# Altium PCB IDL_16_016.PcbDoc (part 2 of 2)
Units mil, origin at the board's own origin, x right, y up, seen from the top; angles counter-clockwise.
Board outline 4921.26 x 4921.26 mil, 4 copper layers (Top Layer - SIG1, MID1_GND, MID2_PWR, Bottom Layer - SIG2), stack 60.174 mil thick; 186 components, 167 nets, 650 pads, 188 vias.
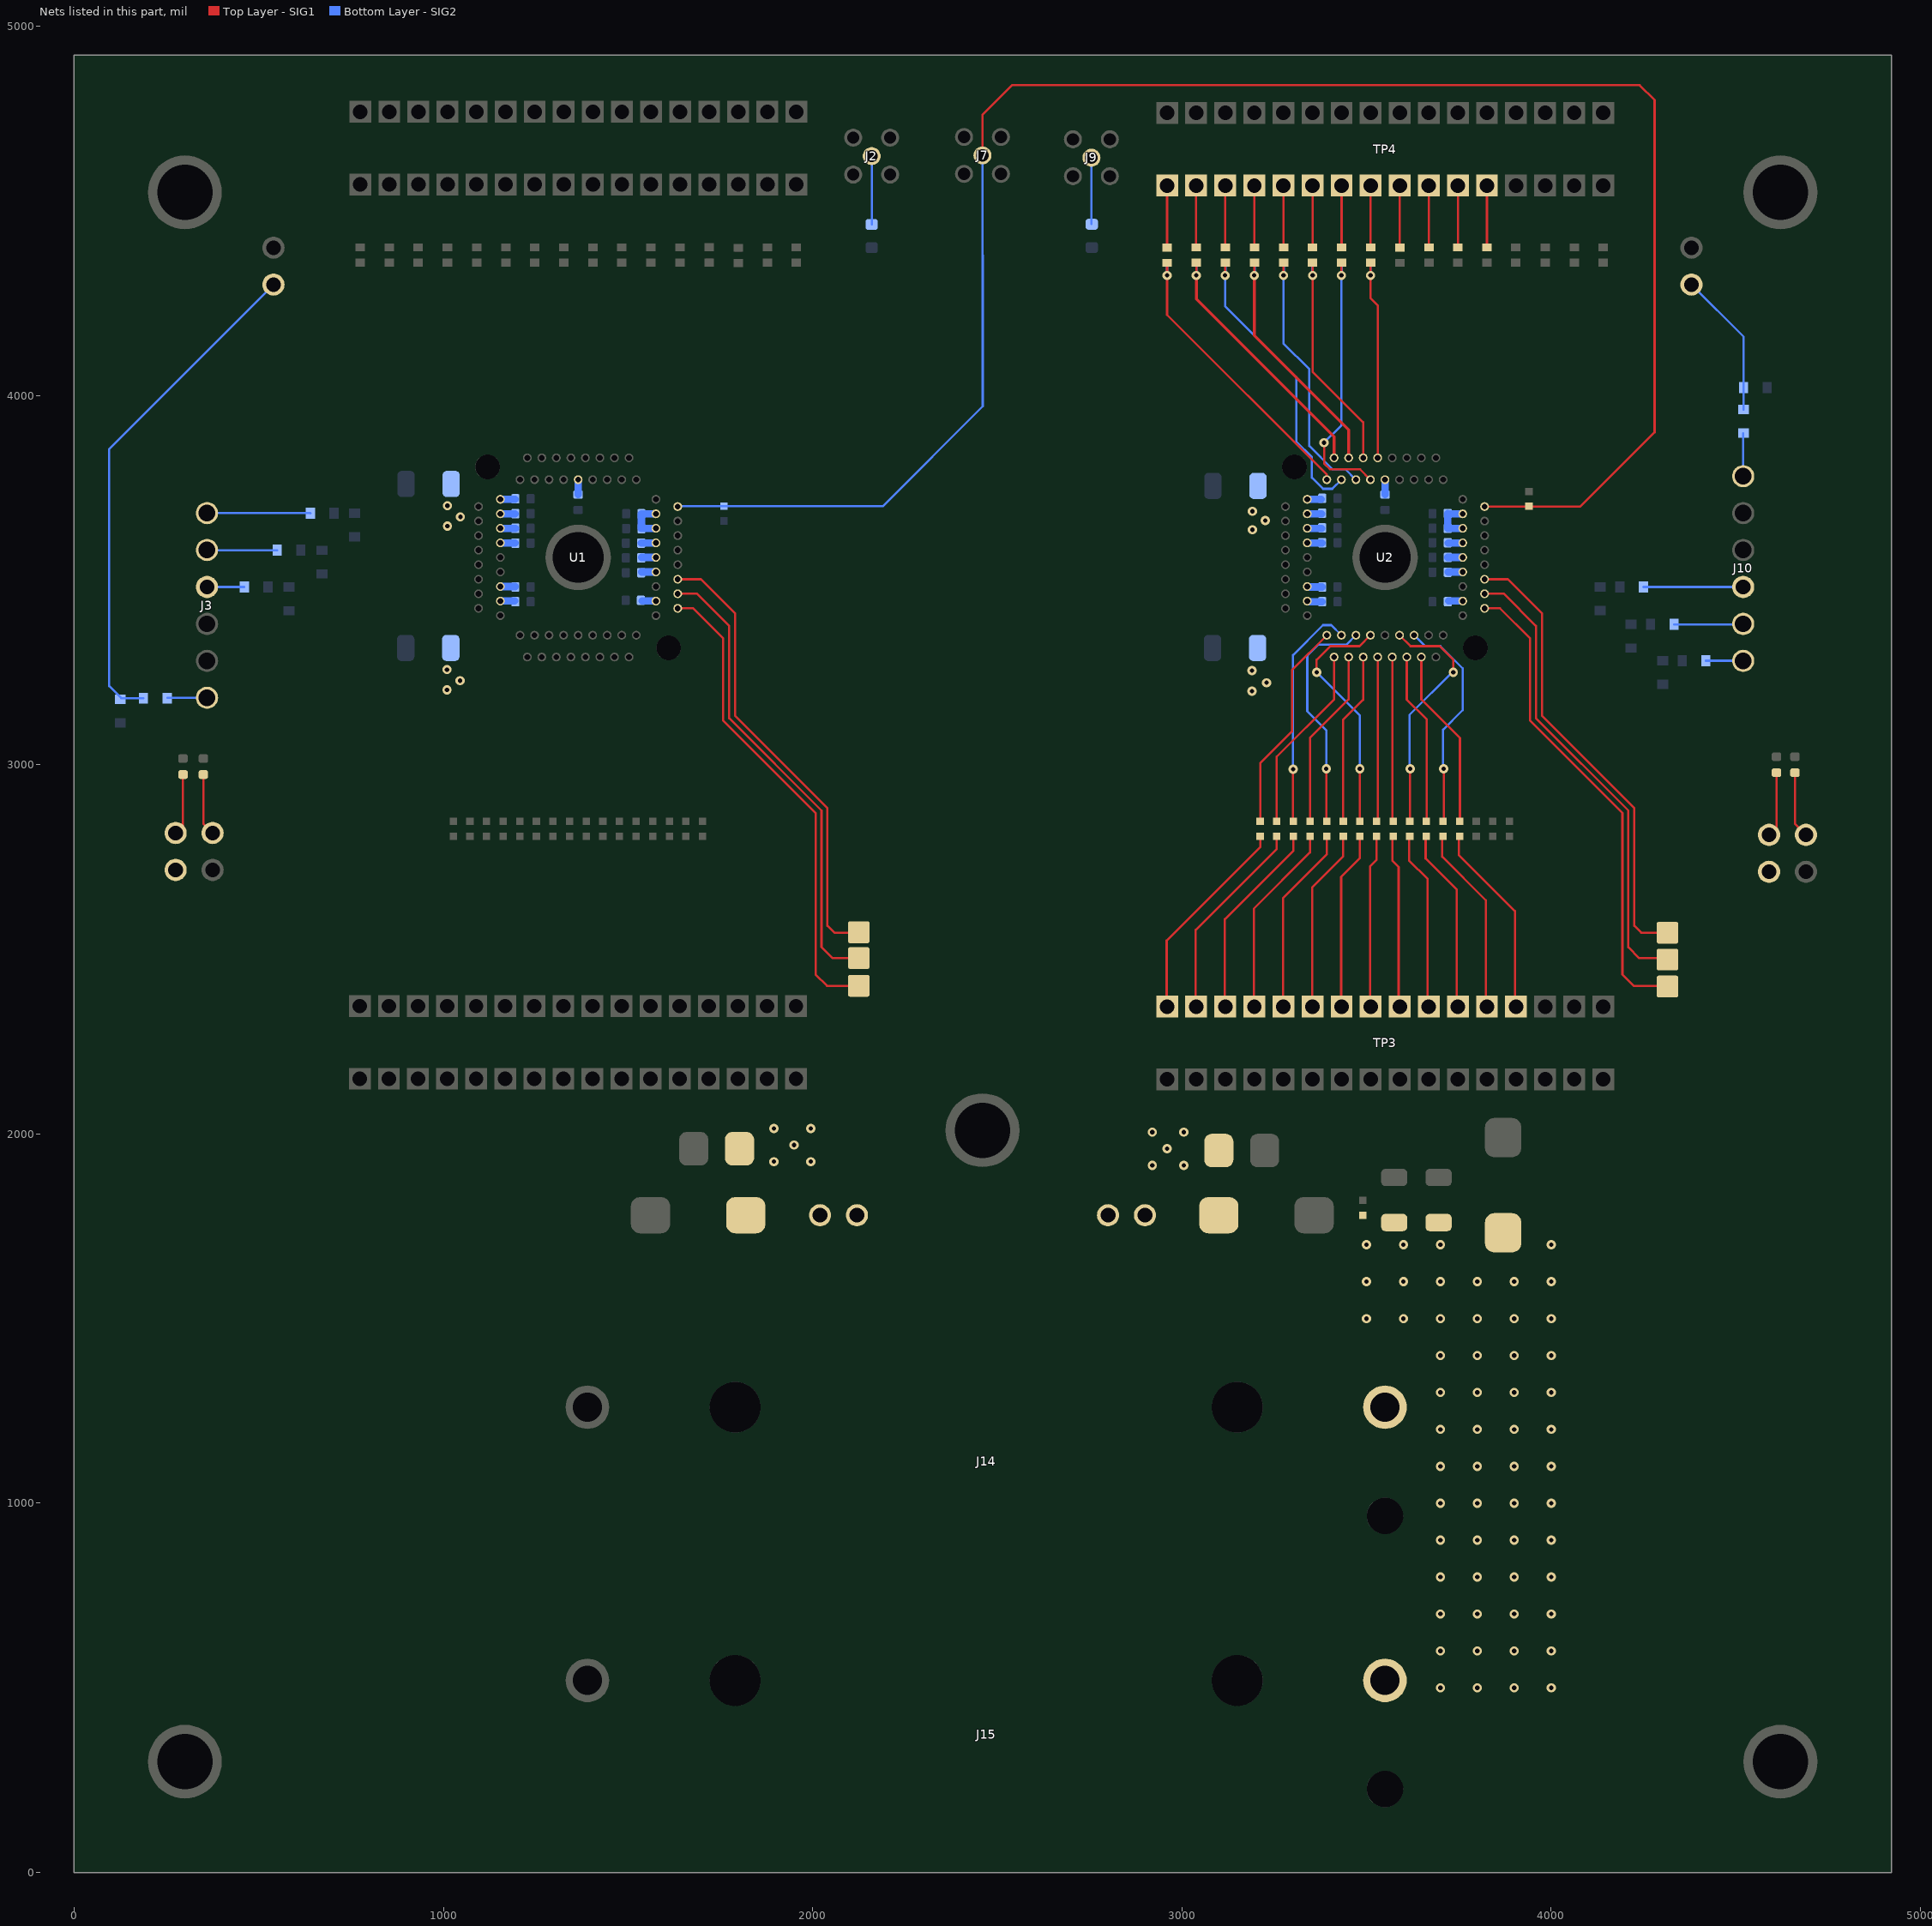
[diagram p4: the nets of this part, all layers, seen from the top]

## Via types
v1: diameter 25, hole 12, Top Layer - SIG1 to Bottom Layer - SIG2, 188 vias

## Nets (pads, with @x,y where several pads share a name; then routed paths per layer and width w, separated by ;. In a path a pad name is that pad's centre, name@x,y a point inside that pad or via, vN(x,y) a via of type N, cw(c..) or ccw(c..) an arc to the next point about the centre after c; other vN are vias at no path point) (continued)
NetC98_1: C98.1 U2.48 | length 488.6
  Top Layer - SIG1 w6: U2.48@3648.43,3291.58 3648.43,3176.58 3753,3072 C98.1@3753,2846.26
NetC98_2: C98.2 TP3.29 | length 522.9
  Top Layer - SIG1 w6: C98.2@3750,2800 3750,2755.74 3901.96,2603.78 TP3.29@3901.96,2340
NetC99_1: C99.1 TP4.5 | length 170.4
  Top Layer - SIG1 w6: C99.1@3826.14,4397.71 TP4.5@3826.14,4568.15
NetC100_1: C100.1 U2.47 | length 606.5
  Top Layer - SIG1 w6: C100.1@3708,2846.26 3709,2847.26 v1(3709,2989)
  Bottom Layer - SIG2 w6: U2.47@3627.11,3352.26 3658.37,3321 3700.06,3321 3760.5,3260.56 3760.5,3147.76 3707.37,3094.63 v1@3707.37,2990.63
NetC100_2: C100.2 TP3.28 | length 509
  Top Layer - SIG1 w6: C100.2@3705,2800 3705,2750.74 3823.22,2632.52 TP3.28@3823.22,2340
NetC101_1: C101.1 TP4.6 | length 170.2
  Top Layer - SIG1 w6: C101.1@3747.4,4397.97 TP4.6@3747.4,4568.15
NetC102_1: C102.1 U2.46 | length 467.7
  Top Layer - SIG1 w6: U2.46@3609.06,3291.58 3609.06,3175.95 3663,3122 C102.1@3663,2846.26
NetC102_2: C102.2 TP3.27 | length 495
  Top Layer - SIG1 w6: C102.2@3660,2800 3660,2745.74 3744.48,2661.26 TP3.27@3744.48,2340
NetC103_1: C103.1 TP4.7 | length 170.7
  Top Layer - SIG1 w6: C103.1@3668.11,4397.68 3668.66,4398.23 TP4.7@3668.66,4568.15
NetC104_1: C104.1 U2.45 | length 659.4
  Top Layer - SIG1 w6: U2.45@3589.37,3350.63 3619,3321 3698,3321 3735,3284 v1(3735,3250) ; C104.1@3618,2846.26 v1(3618,2989)
  Bottom Layer - SIG2 w6: v1@3616.37,2990.63 3616.37,3134.63 v1@3733.37,3251.63
NetC104_2: C104.2 TP3.26 | length 481
  Top Layer - SIG1 w6: C104.2@3615,2800 3615,2740.74 3665.74,2690 TP3.26@3665.74,2340
NetC105_1: C105.1 TP4.8 | length 170.5
  Top Layer - SIG1 w6: TP4.8@3589.92,4568.15 3589.92,4397.87 C105.1@3590.11,4397.68
NetC106_1: C106.1 U2.44 | length 446.3
  Top Layer - SIG1 w6: U2.44@3569.69,3291.58 3569.69,2848.58 C106.1@3572,2846.26
NetC106_2: C106.2 TP3.25 | length 467
  Top Layer - SIG1 w6: C106.2@3570,2800 3570,2740 3587,2723 TP3.25@3587,2340
NetC107_1: C107.1 TP4.9 | length 170.2
  Top Layer - SIG1 w6: C107.1@3511.11,4398.01 3511.18,4398.08 TP4.9@3511.18,4568.15
NetC107_2: C107.2 C117.2 U2.10 | length 571.7
  Top Layer - SIG1 w6: C107.2@3511,4359.66 C107.2@3511,4359.33 v1(3511,4325) 3511,4263 3530.31,4243.68 U2.10@3530.32,3830.95
  Bottom Layer - SIG2 w6: v1(3511,4325) C117.2@3511,4360
NetC108_1: C108.1 U2.42 | length 446.7
  Top Layer - SIG1 w6: C108.1@3527,2846.26 3530.32,2849.58 U2.42@3530.32,3291.58
NetC108_2: C108.2 TP3.24 | length 467
  Top Layer - SIG1 w6: TP3.24@3510,2346.26 3510,2725 3527,2742 C108.2@3527,2806.26
NetC109_1: C109.1 TP4.10 | length 170.6
  Top Layer - SIG1 w6: C109.1@3432.11,4397.68 3432.44,4398.01 TP4.10@3432.44,4568.15
NetC109_2: C109.2 C118.2 U2.11 | length 740.7
  Top Layer - SIG1 w6: v1(3385,3872) 3385,3816 3401,3800 3482.52,3800 U2.11@3510.63,3771.89 ; v1(3432,4325) C109.2@3432,4359.33
  Bottom Layer - SIG2 w6: v1(3385,3872) 3432,3919 v1(3432,4325) ; v1@3433,4326 C118.2@3433,4360
NetC110_1: C110.1 U2.41 | length 659.4
  Top Layer - SIG1 w6: v1(3365,3250) 3365,3284 3402,3321 3481,3321 U2.41@3510.63,3350.63 ; C110.1@3482,2846.26 v1(3482,2989)
  Bottom Layer - SIG2 w6: v1(3365,3250) 3482,3133 v1(3482,2989)
NetC110_2: C110.2 TP3.23 | length 481
  Top Layer - SIG1 w6: TP3.23@3431.26,2346.26 3431.26,2696.26 3482,2747 C110.2@3482,2806.26
NetC111_1: C111.1 TP4.11 | length 170.6
  Top Layer - SIG1 w6: TP4.11@3353.7,4568.15 3353.7,4398.09 C111.1@3354.11,4397.68
NetC111_2: C111.2 C119.2 U2.12 | length 619
  Top Layer - SIG1 w6: C111.2@3354,4359.33 v1(3354,4325) 3354,4064 3490.94,3927.05 U2.12@3490.95,3830.95
  Bottom Layer - SIG2 w6: v1@3353,4326 C119.2@3353,4359.92
NetC112_1: C112.1 U2.40 | length 467.7
  Top Layer - SIG1 w6: C112.1@3437,2846.26 3437,3122 3490.95,3175.95 U2.40@3490.95,3291.58
NetC112_2: C112.2 TP3.22 | length 495
  Top Layer - SIG1 w6: TP3.22@3352.52,2346.26 3352.52,2667.52 3437,2752 C112.2@3437,2806.26
NetC113_1: C113.1 TP4.12 | length 170.5
  Top Layer - SIG1 w6: TP4.12@3274.96,4568.15 3274.96,4397.83 C113.1@3275.11,4397.68
NetC113_2: C113.2 C120.2 U2.13 | length 723.3
  Top Layer - SIG1 w6: v1(3275,4325) C113.2@3275,4359.33
  Bottom Layer - SIG2 w6: v1(3275,4325) 3275,4141 3345,4071 3345,3863.06 3408.06,3800 3443.15,3800 U2.13@3471.26,3771.89 ; v1@3276,4326 C120.2@3276,4360
NetC114_1: C114.1 U2.39 | length 625.6
  Top Layer - SIG1 w6: v1(3391,2989) 3391,2847.26 C114.1@3392,2846.26
  Bottom Layer - SIG2 w6: v1(3391,2989) 3391,3093 3339.5,3144.5 3339.5,3295.5 3369,3325 3445.63,3325 U2.39@3471.26,3350.63
NetC114_2: C114.2 TP3.21 | length 509
  Top Layer - SIG1 w6: TP3.21@3273.78,2346.26 3273.78,2638.78 3392,2757 C114.2@3392,2806.26
NetC115_1: C115.1 TP4.13 | length 170.5
  Top Layer - SIG1 w6: C115.1@3196.11,4397.68 3196.22,4397.79 TP4.13@3196.22,4568.15
NetC115_2: C115.2 C121.2 U2.14 | length 668.2
  Top Layer - SIG1 w6: v1(3196,4325) C115.2@3196,4359.33
  Top Layer - SIG1 w8: v1(3196,4325) 3196,4162 3451.57,3906.42 U2.14@3451.58,3830.95
  Bottom Layer - SIG2 w6: v1@3197,4326 C121.2@3197,4360
NetC116_1: C116.1 U2.38 | length 488.6
  Top Layer - SIG1 w6: C116.1@3347,2846.26 3347,3072 3451.58,3176.58 U2.38@3451.58,3291.58
NetC116_2: C116.2 TP3.20 | length 522.9
  Top Layer - SIG1 w6: TP3.20@3195.04,2346.26 3195.04,2610.04 3347,2762 C116.2@3347,2806.26
NetC122_2: C122.2 C125.2 U2.15 | length 816
  Top Layer - SIG1 w6: v1(3117,4325) C125.2@3117,4359.33
  Bottom Layer - SIG2 w6: v1(3117,4325) 3117,4242 3310,4049 3310,3875.44 3352,3833.44 3352,3777.32 3382.24,3747.08 3407.08,3747.08 U2.15@3431.89,3771.89 ; v1@3118,4326 C122.2@3118,4359.92
NetC123_2: C123.2 C127.2 U2.16 | length 717.9
  Top Layer - SIG1 w6: v1(3039,4325) C127.2@3039,4359.33
  Top Layer - SIG1 w8: v1(3039,4325) 3039,4261 3412.2,3887.79 U2.16@3412.21,3830.95
  Bottom Layer - SIG2 w6: v1(3039,4325) C123.2@3039,4359.92
NetC124_2: C124.2 C129.2 U2.17 | length 801.5
  Top Layer - SIG1 w6: C129.2@2960,4359.25 C129.2@2960,4359.25 v1(2960,4325) 2960,4218 3392.52,3785.48 U2.17@3392.52,3771.89
  Bottom Layer - SIG2 w6: v1(2960,4325) C124.2@2960,4359.92
NetC125_1: C125.1 TP4.14 | length 170.6
  Top Layer - SIG1 w6: C125.1@3117.11,4397.68 3117.48,4398.05 TP4.14@3117.48,4568.15
NetC126_1: C126.1 U2.37 | length 626.9
  Top Layer - SIG1 w6: v1(3301,2988) 3301,2847.26 C126.1@3302,2846.26
  Bottom Layer - SIG2 w6: v1(3301,2988) 3301,3297 3382,3378 3404.52,3378 U2.37@3431.89,3350.63
NetC126_2: C126.2 TP3.19 | length 536.9
  Top Layer - SIG1 w6: TP3.19@3116.3,2346.26 3116.3,2581.3 3302,2767 C126.2@3302,2806.26
NetC127_1: C127.1 TP4.15 | length 170.6
  Top Layer - SIG1 w6: TP4.15@3038.74,4568.15 3038.74,4398.06 C127.1@3039.11,4397.68
NetC128_1: C128.1 U2.36 | length 509.6
  Top Layer - SIG1 w6: C128.1@3257,2846.26 3257,3022 3412.21,3177.21 U2.36@3412.21,3291.58
NetC128_2: C128.2 TP3.18 | length 550.9
  Top Layer - SIG1 w6: TP3.18@3037.56,2346.26 3037.56,2552.56 3257,2772 C128.2@3257,2806.26
NetC129_1: C129.1 TP4.16 | length 170.7
  Top Layer - SIG1 w6: C129.1@2960.11,4397.68 2960,4397.8 C129.1@2960,4400.59 TP4.16@2960,4568.15 TP4.16@2960.11,4568.04
NetC130_1: C130.1 U2.35 | length 579.1
  Top Layer - SIG1 w6: C130.1@3212,2846.26 3212,3004 3298,3090 3298,3256.11 U2.35@3392.52,3350.63
NetC130_2: C130.2 TP3.17 | length 564.9
  Top Layer - SIG1 w6: TP3.17@2958.82,2346.26 2958.82,2523.82 3212,2777 C130.2@3212,2806.26
NetCSA1_ADC_out_1: CSA1_ADC_out.1 U1.53 | length 1300.3
  Top Layer - SIG1 w6: U1.53@1634.69,3423.47 1676.53,3423.47 1758,3342 1758,3119.12 2008,2869.12 2008,2432 2038.74,2401.26 CSA1_ADC_out.1@2125,2401.26
NetCSA1_DAC_out_1: CSA1_DAC_out.1 U1.55 | length 1262.2
  Top Layer - SIG1 w6: U1.55@1634.69,3462.83 1687.17,3462.83 1774,3376 1774,3125.75 2024,2875.75 2024,2506 2053.74,2476.26 CSA1_DAC_out.1@2125,2476.26
NetCSA1_SPYLINE_1: CSA1_SPYLINE.1 U1.57 | length 1240.9
  Top Layer - SIG1 w6: U1.57@1634.69,3502.21 1697.79,3502.21 1790,3410 1790,3132.37 2040,2882.37 2040,2564 2059,2545 CSA1_SPYLINE.1@2130,2545
NetCSA2_ADC_out_1: CSA2_ADC_out.1 U2.57 | length 1240.9
  Top Layer - SIG1 w6: U2.57@3819.69,3502.21 3882.79,3502.21 3975,3410 3975,3132.37 4225,2882.37 4225,2564 4244,2545 CSA2_ADC_out.1@4315,2545
NetCSA2_DAC_out_1: CSA2_DAC_out.1 U2.55 | length 1262.2
  Top Layer - SIG1 w6: U2.55@3819.69,3462.83 3872.16,3462.83 3959,3376 3959,3125.75 4209,2875.75 4209,2506 4238.74,2476.26 CSA2_DAC_out.1@4310,2476.26
NetCSA2_SPYLINE_1: CSA2_SPYLINE.1 U2.53 | length 1300.3
  Top Layer - SIG1 w6: U2.53@3819.69,3423.47 3861.54,3423.47 3943,3342 3943,3119.12 4193,2869.12 4193,2432 4223.74,2401.26 CSA2_SPYLINE.1@4310,2401.26
NetJ2_1: J2.1 R1.1 | length 185
  Bottom Layer - SIG2 w6: J2.1@2159.89,4647.99 2160,4647.87 R1.1@2160,4462.99
NetJ3_1: J3.1 R3.1 | length 280.1
  Bottom Layer - SIG2 w6: J3.1@360,3681.26 639.74,3681.26 R3.1@640,3681
NetJ3_2: J3.2 R2.1 | length 189.7
  Bottom Layer - SIG2 w6: J3.2@360.26,3581 R2.1@550,3581
NetJ3_3: J3.3 R4.1 | length 101
  Bottom Layer - SIG2 w6: J3.3@360,3481.26 R4.1@461,3481.26
NetJ3_6: J3.6 R10.2 | length 106.7
  Bottom Layer - SIG2 w6: R10.2@253.26,3181.26 J3.6@360,3181.26
NetJ4_2: J4.2 R10.1 R11.1 | length 1378
  Bottom Layer - SIG2 w6: R10.1@188,3180 128,3180 95,3213 95,3855 J4.2@540,4300
NetJ5_2: J5.2 R8.2 | length 166.6
  Top Layer - SIG1 w6: J5.2@275,2815 295,2835 R8.2@295,2973.35
NetJ6_1: J6.1 R9.1 | length 168.7
  Top Layer - SIG1 w6: R9.1@350,2973.35 350,2840 J6.1@375,2815
NetJ9_1: J9.1 R12.1 | length 179.2
  Bottom Layer - SIG2 w6: R12.1@2755,4464.5 J9.1@2755,4643.74
NetJ10_1: J10.1 R15.1 | length 100.8
  Bottom Layer - SIG2 w6: R15.1@4419,3281.5 J10.1@4519.76,3281.5
NetJ10_2: J10.2 R14.1 | length 185.7
  Bottom Layer - SIG2 w6: R14.1@4333,3380 J10.2@4518.74,3380
NetJ10_3: J10.3 R16.1 | length 270
  Bottom Layer - SIG2 w6: R16.1@4250,3481.26 J10.3@4520,3481.26
NetJ10_6: J10.6 R22.2 | length 115.7
  Bottom Layer - SIG2 w6: J10.6@4520,3781.26 R22.2@4520,3897
NetJ11_2: J11.2 R22.1 R23.1 | length 396.4
  Bottom Layer - SIG2 w6: J11.2@4380,4300 4521,4159 R23.1@4521,4021 R22.1@4521,3962
NetJ12_2: J12.2 R20.2 | length 176.6
  Top Layer - SIG1 w6: J12.2@4590,2810 4610,2830 R20.2@4610,2978.35
NetJ13_1: J13.1 R21.1 | length 180.8
  Top Layer - SIG1 w6: R21.1@4660,2978.35 4660,2840 J13.1@4690,2810
PWR: C131.1 C132.2 C133.2 C134.2 J1.1 J8.1 J14.2 J15.2
  other v1: 3700,500 3800,500 3900,500 4000,500 3700,600 3800,600 3900,600 4000,600 3700,700 3800,700 3900,700 4000,700 3700,800 3800,800 3900,800 4000,800 3700,900 3800,900 3900,900 4000,900 3700,1000 3800,1000 3900,1000 4000,1000 3700,1100 3800,1100 3900,1100 4000,1100 3700,1200 3800,1200 3900,1200 4000,1200 3700,1300 3800,1300 3900,1300 4000,1300 3700,1400 3800,1400 3900,1400 4000,1400 3500,1500 3600,1500 3700,1500 3800,1500 3900,1500 4000,1500 3500,1600 3600,1600 3700,1600 3800,1600 3900,1600 4000,1600 3500,1700 3600,1700 3700,1700 4000,1700
PWR1: C1.1 C2.1 C3.1 C4.1 C5.1 C6.1 C7.1 C8.1 C9.1 C10.2 C11.2 C12.2 C13.2 C14.2 C15.2 C16.2 C17.2 J1.2 J5.1 U1.9 U1.18 U1.20 U1.22 U1.24 U1.30 U1.32 U1.54 U1.58 U1.60 U1.62 U1.64 U1.66 | length 550.9
  Bottom Layer - SIG2 w20: U1.32@1154.37,3443.15 C12.2@1193.11,3443.15 ; U1.30@1154.37,3482.52 C11.2@1193.74,3482.52 ; U1.24@1154.37,3600.63 C8.1@1194.37,3600.63 ; U1.22@1154.37,3640 C7.1@1195,3640 ; U1.20@1154.37,3679.37 C6.1@1194.37,3679.37 ; U1.18@1154.37,3718.74 C5.1@1193.74,3718.74 ; C4.1@1365,3731.26 U1.9@1365,3771.89 ; C17.2@1535.67,3640 C17.2@1536.3,3640 ; C16.2@1536.3,3600.63 U1.62@1575.63,3600.63 ; C17.2@1536.3,3639.37 C17.2@1536.3,3640 ; C15.2@1536.93,3561.26 U1.60@1575.63,3561.26 ; C14.2@1537.56,3521.89 U1.58@1575.63,3521.89 ; C13.2@1538.82,3443.15 U1.54@1575.63,3443.15 ; U1.64@1575.63,3640 C17.2@1536.3,3640 ; U1.66@1575.63,3679.37 C9.1@1536.3,3679.37 C17.2@1536.3,3640
  other v1: 1895,1925 1995,1925 1950,1970 1895,2015 1995,2015 1010,3202.52 1045,3227.52 1010,3257.52 1011.02,3646.26 1046.02,3671.26 1011.02,3701.26
PWR2: C66.1 C67.1 C68.1 C69.1 C70.1 C71.1 C72.1 C73.1 C74.1 C75.2 C76.2 C77.2 C78.2 C79.2 C80.2 C81.2 C82.2 J8.2 J12.1 U2.9 U2.18 U2.20 U2.22 U2.24 U2.30 U2.32 U2.54 U2.58 U2.60 U2.62 U2.64 U2.66 | length 555
  Bottom Layer - SIG2 w20: U2.24@3339.37,3600.63 C73.1@3379.37,3600.63 ; U2.22@3339.37,3640 C72.1@3378.74,3640 ; U2.20@3339.37,3679.37 C71.1@3378.11,3679.37 ; U2.18@3339.37,3718.74 C69.1@3377.48,3718.74 ; U2.30@3340.63,3481.26 C76.2@3380,3481.26 ; U2.32@3341.26,3441.26 C77.2@3380,3441.26 ; C70.1@3550,3731.26 U2.9@3550,3771.89 ; C80.2@3720,3561.26 U2.60@3760.63,3561.26 ; C74.1@3720,3680 C82.2@3720,3640 U2.64@3760.63,3640 ; C79.2@3720.63,3521.89 U2.58@3760.63,3521.89 ; C81.2@3720.63,3600.63 U2.62@3760.63,3600.63 ; C74.1@3720.63,3679.37 U2.66@3760.63,3679.37 ; C78.2@3721.89,3443.15 U2.54@3760.63,3443.15
  other v1: 2920,1915 3005,1915 2960,1960 2920,2005 3005,2005 3190,3199 3229,3222 3190,3255 3191.02,3636.26 3226.02,3661.26 3191.02,3686.26
"TEST SIGNAL": J7.1 R13.2 R24.2 U1.67 U2.67 | length 5040.4
  Top Layer - SIG1 w6: J7.1@2460,4650 2460,4760 2540,4840 4240,4840 4280,4800 4280,3900 4079.06,3699.06 U2.67@3819.69,3699.06
  Bottom Layer - SIG2 w6: U1.67@1634.69,3699.06 1635.63,3700 2190,3700 2460.63,3970.63 2460.63,4379.92 ; 2460,4380.55 J7.1@2460,4650
pads on no net: J14.3 J14.4 J14.5 J15.3 J15.4 J15.5 U1.70 U1.71 U2.70 U2.71

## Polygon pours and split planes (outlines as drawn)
no net on Bottom Layer - SIG2 "Bottom_PWR1_2" (solid, pour order 30): 3170,3361.54 3245,3361.54 3245,3187.52 3230,3172.52 3190,3172.52 3185,3172.52 3170,3187.52
GND on Bottom Layer - SIG2 "Bot_GND3" (solid, pour order 24): 3685,3410 3410,3410 3410,3411.58 3400,3421.58 3400.67,3422.24 3400.67,3730.83 3400.67,3735.67 3410,3745 3460,3745 3470,3735 3494.41,3710.59 3539.17,3710.59 3689.41,3710.59 3690,3710 3700.63,3699.37 3700.63,3685 3700.63,3425.63 3685,3410
GND on Bottom Layer - SIG2 "Bot_GND4" (solid, pour order 20): 3045.99,3361.54 3120.99,3361.54 3120.99,3187.52 3105.98,3172.52 3065.99,3172.52 3060.99,3172.52 3045.98,3187.52
GND on Bottom Layer - SIG2 "Bot_GND5" (solid, pour order 18): 3050.95,3800.28 3125.95,3800.28 3125.95,3626.26 3110.94,3611.26 3070.95,3611.26 3065.95,3611.26 3050.94,3626.26
GND on Bottom Layer - SIG2 "Bot_GND2" (solid, pour order 16): 863.98,3805.28 938.98,3805.28 938.98,3631.26 923.98,3616.26 883.98,3616.26 878.98,3616.26 863.98,3631.26
GND on Bottom Layer - SIG2 "Bot_GND1" (solid, pour order 14): 862.95,3361.54 937.95,3361.54 937.95,3187.52 922.95,3172.52 882.95,3172.52 877.95,3172.52 862.95,3187.52
GND on Bottom Layer - SIG2 "Bot_GND" (solid, pour order 12): 1500,3410 1225,3410 1225,3411.58 1215,3421.58 1215.67,3422.24 1215.67,3730.83 1215.67,3735.67 1225,3745 1275,3745 1285,3735 1309.41,3710.59 1354.17,3710.59 1504.41,3710.59 1505,3710 1515.63,3699.37 1515.63,3685 1515.63,3425.63 1500,3410
PWR2 on Bottom Layer - SIG2 "Bottom_PWR2_1" (solid, pour order 9): 3170,3361.54 3245,3361.54 3245,3187.52 3230,3172.52 3190,3172.52 3185,3172.52 3170,3187.52
PWR2 on Bottom Layer - SIG2 "Bottom_PWR2_1" (solid, pour order 8): 3171.02,3800.28 3246.02,3800.28 3246.02,3626.26 3231.02,3611.26 3191.02,3611.26 3186.02,3611.26 3171.02,3626.26
PWR1 on Bottom Layer - SIG2 "Bottom_PWR1_2" (solid, pour order 7): 985,3361.54 1060,3361.54 1060,3187.52 1045,3172.52 1005,3172.52 1000,3172.52 985,3187.52
PWR1 on Bottom Layer - SIG2 "Bottom_PWR1_1" (solid, pour order 6): 986.02,3805.28 1061.02,3805.28 1061.02,3631.26 1046.02,3616.26 1006.02,3616.26 1001.02,3616.26 986.02,3631.26
PWR2 on Top Layer - SIG1 "Top_PWR2" (solid, pour order 36): 3575,3760 3575,3780 3565,3790 3535,3790 3525,3780 3525,3750 3515,3740 3335,3740 3325,3730 3325,3590 3335,3580 3355,3580 3365,3590 3365,3700.31 3365.32,3700.31 3375,3710 3475,3710 3565,3710 3575,3720
PWR1 on Top Layer - SIG1 "Top_PWR1" (solid, pour order 34): 1390,3760 1390,3780 1380,3790 1350,3790 1340,3780 1340,3750 1330,3740 1150,3740 1140,3730 1140,3590 1150,3580 1170,3580 1180,3590 1180,3700.31 1180.32,3700.31 1190,3710 1290,3710 1380,3710 1390,3720
GND on Top Layer - SIG1 "Top_GND1" (solid, pour order 26): 1250,1680 1680,1680 1710,1710 1730,1730 1730,1910 1730,1990 1680,2040 1250,2040 1240,2040 1210,2010 1200,2000 1200,1770 1200,1730 1250,1680
PWR on Top Layer - SIG1 "Top_PWR_1" (solid, pour order 0): 4050,420 4050,1780 4030,1800 3470,1800 3450,1780 3450,420 3470,400 4030,400
PWR1 on Top Layer - SIG1 "Top_PWR1_1" (solid, pour order 2): 1751.25,1728.75 1798.43,1681.58 2002.83,1681.58 2050,1728.75 2050,2027.5 2035,2042.5 1807.38,2042.5 1754.64,1989.76
PWR2 on Top Layer - SIG1 "Top_PWR2_1" (solid, pour order 3): 3160,1710 3130,1680 2890,1680 2860,1710 2860,2014.99 2893.32,2040 3130,2040 3160,2010
GND on Top Layer - SIG1 "Top_GND2" (solid, pour order 28): 3170,2010 3170,2020 3190,2040 3350,2040 3950,2040 3980,2010 3980,1880 3950,1850 3563.5,1850 3543.5,1830 3523.5,1810 3510,1810 3440,1810 3430,1800 3430,1750 3430,1710 3420,1700 3230,1700 3170,1760 3170,2017.99
GND on MID1_GND (split plane): 4901.16,20.1 20.1,20.1 20.1,4901.16 4901.16,4901.16
PWR2 on MID2_PWR (split plane): 3777.91,3697.82 3777.91,3655 3778.26,3652.39 3779.27,3649.96 3780.87,3647.87 3845.87,3582.87 3847.96,3581.26 3849.17,3580.76 3850.39,3580.26 3853,3579.91 4901.16,3579.91 4901.16,1794.18 3104.09,1794.18 3101.48,1793.83 3099.05,1792.83 3096.96,1791.22 3005.82,1700.09 2894.18,1700.09 2860.09,1734.18 2860.09,1830.01 2860.09,2000 2860.09,2300 2860.09,3605.82 2962.18,3707.91 3767.82,3707.91
PWR1 on MID2_PWR (split plane): 202.87,3722.87 204.96,3721.26 206.68,3720.55 207.39,3720.26 210,3719.91 1555.82,3719.91 1584.18,3691.56 1584.18,3670.17 1584.52,3667.56 1585.53,3665.13 1587.13,3663.04 1607.3,3642.87 1609.39,3641.26 1610.11,3640.97 1611.83,3640.26 1614.44,3639.91 2025.82,3639.91 2054.91,3610.82 2054.91,3605 2054.91,2291.38 2054.91,1727.68 2007.32,1680.09 214.18,1680.09 20.1,1874.17 20.1,3745.65 180.09,3745.65
PWR on MID2_PWR (split plane): 4901.16,3600.09 3857.18,3600.09 3798.09,3659.18 3798.09,3702 3797.74,3704.61 3796.74,3707.04 3795.13,3709.13 3779.13,3725.13 3777.04,3726.74 3774.61,3727.74 3772,3728.09 2963.2,3728.09 2961.61,3728.74 2959,3729.09 2956.39,3728.74 2953.96,3727.74 2951.87,3726.13 2842.87,3617.13 2841.27,3615.04 2840.26,3612.61 2839.91,3610 2839.91,2300 2839.91,2000 2839.91,1830.01 2839.91,1730 2840.26,1727.39 2841.27,1724.96 2842.87,1722.87 2882.87,1682.87 2884.96,1681.26 2886.68,1680.55 2887.39,1680.26 2890,1679.91 3010,1679.91 3012.61,1680.26 3015.04,1681.26 3017.13,1682.87 3108.27,1774.01 4901.16,1774.01 4901.16,20.1 20.1,20.1 20.1,1845.64 202.87,1662.87 204.96,1661.26 207.39,1660.26 210,1659.91 2011.5,1659.91 2014.11,1660.26 2016.54,1661.26 2018.63,1662.87 2072.13,1716.37 2073.73,1718.46 2074.45,1720.18 2074.74,1720.89 2075.09,1723.5 2075.09,2291.38 2075.09,3605 2075.09,3615 2074.74,3617.61 2074.03,3619.33 2073.73,3620.04 2072.13,3622.13 2037.13,3657.13 2035.04,3658.74 2032.61,3659.74 2030,3660.09 1618.61,3660.09 1604.35,3674.35 1604.35,3695.74 1604.01,3698.35 1603,3700.78 1601.4,3702.87 1567.13,3737.13 1565.04,3738.74 1562.61,3739.74 1560,3740.09 214.18,3740.09 191.4,3762.87 189.31,3764.47 186.87,3765.48 184.26,3765.82 20.1,3765.82 20.1,4901.16 4901.16,4901.16

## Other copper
Top Layer - SIG1:
  text "L1" at 50,60 h30
Bottom Layer - SIG2:
  text "L4" at 50,60 h30
MID1_GND (plane layer: these items are gaps in the copper):
  text "L2" at 50,60 h30
MID2_PWR (plane layer: these items are gaps in the copper):
  lines w20: 0,1880 210,1670 2011.5,1670 2065,1723.5 2065,2291.38 2065,3605 2065,3615 2030,3650 1614.44,3650 1594.26,3670.17 1594.26,3695.74 1560,3730 210,3730 184.26,3755.74 0,3755.74 ; 2959,3718 3532,3718 3602,3718 3772,3718 3788,3702 3788,3655 3853,3590 3980,3590 4921.26,3590 ; 2959,3719 2850,3610 2850,2300 2850,2000 2850,1830.01 2850,1730 2890,1690 3010,1690 3104.09,1784.09 3120,1784.09 ; 3106,1784.09 4921.26,1784.09
  text "L3" at 50,60 h30

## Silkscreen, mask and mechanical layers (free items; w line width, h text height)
Top Overlay:
  lines w10: 2035,4365 2020,4380 ; 2035,4395 2020,4380 ; 2060,4380 2020,4380 ; 2097.5,2807.5 2082.5,2822.5 ; 2097.5,2837.5 2082.5,2822.5 ; 2122.5,2822.5 2082.5,2822.5 ; 2850,2820 2890,2820 ; 2855.49,4380 2895.49,4380 ; 2875,2805 2890,2820 ; 2875,2835 2890,2820 ; 2880.49,4365 2895.49,4380 ; 2880.49,4395 2895.49,4380
  text "TS" at 2440,4750 h25
  text "CSA1_Test" at 2059.77,4745.98 h25
  text "CSA2_Test" at 2649.88,4742.99 h25
  text "GND" at 520.01,4739.99 h60
  text "GND" at 4225,4735 h60
  text "INPUT" at 415.01,4539.99 h60
  text "INPUT" at 4219.84,4535 h60
  text "CH16" at 760.01,4529.99 h25 r270
  text "CH15" at 840.01,4529.99 h25 r270
  text "CH14" at 920.01,4529.99 h25 r270
  text "CH13" at 1000.01,4529.99 h25 r270
  text "CH12" at 1080.01,4529.99 h25 r270
  text "CH11" at 1155.01,4529.99 h25 r270
  text "CH10" at 1235.01,4529.99 h25 r270
  text "CH9" at 1315.01,4529.99 h25 r270
  text "CH8" at 1395.01,4529.99 h25 r270
  text "CH7" at 1470.01,4529.99 h25 r270
  text "CH6" at 1550.01,4529.99 h25 r270
  text "CH5" at 1630.01,4529.99 h25 r270
  text "CH4" at 1710.01,4529.99 h25 r270
  text "CH3" at 1785.01,4529.99 h25 r270
  text "CH2" at 1865.01,4529.99 h25 r270
  text "CH1" at 1945.01,4529.99 h25 r270
  text "CH16" at 2945.12,4527.01 h25 r270
  text "CH15" at 3025.12,4527.01 h25 r270
  text "CH14" at 3105.12,4527.01 h25 r270
  text "CH13" at 3185.12,4527.01 h25 r270
  text "CH12" at 3265.12,4527.01 h25 r270
  text "CH11" at 3340.12,4527.01 h25 r270
  text "CH10" at 3420.12,4527.01 h25 r270
  text "CH9" at 3500.12,4527.01 h25 r270
  text "CH8" at 3580.12,4527.01 h25 r270
  text "CH7" at 3655.12,4527.01 h25 r270
  text "CH6" at 3735.12,4527.01 h25 r270
  text "CH5" at 3815.12,4527.01 h25 r270
  text "CH4" at 3895.12,4527.01 h25 r270
  text "CH3" at 3970.12,4527.01 h25 r270
  text "CH2" at 4050.12,4527.01 h25 r270
  text "CH1" at 4130.12,4527.01 h25 r270
  text "Install 0 ohm for DC or 10nF for AC" at 2160,4340 h25
  text "Install to enable  / FPGA test signal" at 50,4320 h25
  text "Install to enable  / FPGA test signal" at 4480,4310 h25
  text "FPGA_TS" at 4670,3760 h30
  text "PCLK" at 90,3666 h30
  text "GND" at 4670,3660 h30
  text "CLK" at 90,3567 h30
  text "SOUT" at 4670,3560 h30
  text "SIN" at 90,3470 h30
  text "SIN" at 4670,3460 h30
  text "SOUT" at 90,3370 h30
  text "CLK" at 4671,3363 h30
  text "GND" at 90,3270 h30
  text "PCLK" at 4671,3266 h30
  text "FPGA_TS" at 20,3170 h30
  text "nCLR" at 4530,2880 h60
  text "nCLR" at 220,2875 h60
  text "Install 100nF cap" at 2270,2800 h25
  text "active low" at 460,2610 h25 r90
  text "active high" at 210,2605 h25 r90
  text "active high" at 4530,2600 h25 r90
  text "active low" at 4780,2600 h25 r90
  text "CH16" at 779.48,2402.99 h25 r90
  text "CH15" at 859.48,2402.99 h25 r90
  text "CH14" at 939.48,2402.99 h25 r90
  text "CH13" at 1019.48,2402.99 h25 r90
  text "CH12" at 1099.48,2402.99 h25 r90
  text "CH11" at 1174.48,2402.99 h25 r90
  text "CH10" at 1254.48,2402.99 h25 r90
  text "CH9" at 1334.48,2402.99 h25 r90
  text "CH8" at 1414.48,2402.99 h25 r90
  text "CH7" at 1489.48,2402.99 h25 r90
  text "CH6" at 1569.48,2402.99 h25 r90
  text "CH5" at 1649.48,2402.99 h25 r90
  text "CH4" at 1729.48,2402.99 h25 r90
  text "CH3" at 1804.48,2402.99 h25 r90
  text "CH2" at 1884.48,2402.99 h25 r90
  text "CH1" at 1964.48,2402.99 h25 r90
  text "CH16" at 2966.3,2392.99 h25 r90
  text "CH15" at 3046.3,2392.99 h25 r90
  text "CH14" at 3126.3,2392.99 h25 r90
  text "CH13" at 3206.3,2392.99 h25 r90
  text "CH12" at 3286.3,2392.99 h25 r90
  text "CH11" at 3361.3,2392.99 h25 r90
  text "CH10" at 3441.3,2392.99 h25 r90
  text "CH9" at 3521.3,2392.99 h25 r90
  text "CH8" at 3601.3,2392.99 h25 r90
  text "CH7" at 3676.3,2392.99 h25 r90
  text "CH6" at 3756.3,2392.99 h25 r90
  text "CH5" at 3836.3,2392.99 h25 r90
  text "CH4" at 3916.3,2392.99 h25 r90
  text "CH3" at 3991.3,2392.99 h25 r90
  text "CH2" at 4071.3,2392.99 h25 r90
  text "CH1" at 4151.3,2392.99 h25 r90
  text "OUTPUT" at 2320,2310 h60
  text "GND" at 2380,2110 h60
  text "CSA1 EN" at 1875,1901.26 h60
  text "CSA2 EN" at 2615,1895 h60
  text "CSA V3 Radiation Board" at 169.37,715.23 h25
  text "IDL_16_016" at 170.77,669.43 h25
  text "AS/KPL" at 170.47,618.23 h25
  text "AA Batteries" at 2100,60 h60
Bottom Overlay:
  lines w10: 2035,4365 2020,4380 ; 2035,4395 2020,4380 ; 2060,4380 2020,4380 ; 2852.01,4379 2892.01,4379 ; 2877.01,4364 2892.01,4379 ; 2877.01,4394 2892.01,4379
  text "Install 50 ohm termination / or 1pF external cap" at 2770,4280 h25
Board Outline:
  the board outline again, w4
Sheet Top:
  lines w3.9: -1558.27,-4760.22 -1558.27,6719.69 14241.64,6719.69 14241.64,-4760.22 -1558.27,-4760.22 ; -1458,-4660.51 -1458,6619.98 14141.38,6619.98 14141.38,-4660.51 -1458,-4660.51
  lines w3.94: 7451.73,-4660.51 7451.73,-3950.31 14141.38,-3950.31 ; 7451.73,-4309.55 14141.73,-4309.55 ; 7451.73,-4190.31 12271.73,-4190.31 ; 7451.73,-4070.31 12271.73,-4070.31 ; 8956.73,-4309.55 8956.73,-3950.31 ; 9956.73,-4309.55 9956.73,-3950.31 ; 11546.73,-4309.55 11546.73,-3950.31 ; 12271.73,-4660.51 12271.73,-3950.31 ; 12271.73,-4130.31 14141.38,-4130.31
  text "Designer:" at 7476.73,-4040.31 h100
  text ".Designer" at 8041.73,-4045.31 h100
  text "Revision:" at 8981.73,-4045.31 h100
  text ".Version" at 9541.73,-4045.31 h100
  text "File:" at 9981.73,-4045.31 h100
  text ".Pcb_File_Name_No_Path" at 10181.73,-4045.31 h100
  text "Sheet  1 of  1" at 11576.73,-4045.31 h100
  text "Code:" at 12296.73,-4090.31 h100
  text "Drawn By:" at 7476.73,-4160.31 h100
  text ".Drawn_By" at 8041.73,-4160.31 h100
  text "Modif. Date:" at 8981.73,-4165.31 h100
  text "Date" at 9486.73,-4165.31 h100
  text "Variant:" at 9981.73,-4165.31 h100
  text ".VariantName" at 10346.73,-4165.31 h100
  text "ID:" at 12301.73,-4270.31 h100
  text "Approved By:" at 7476.73,-4280.31 h100
  text ".Approved_By" at 8041.73,-4280.31 h100
  text "Print Date:" at 8981.73,-4285.31 h100
  text ".Print_Date" at 9486.73,-4285.31 h100
  text "Signature:" at 9981.73,-4285.31 h100
  text "Size:  A3 H" at 11576.73,-4285.31 h100
  text "Title:" at 7476.73,-4410.31 h100
  text "University of Hawaii at Manoa" at 12303.15,-4418.58 h100
  text "High Energy Physics Group" at 12303.15,-4517.01 h100
  text ".Printout_Name" at 7701.73,-4550.31 h160
  text "Instrumentation Development Laboratory" at 12303.15,-4619.37 h100
Sheet Bot:
  lines w3.9: -1558.53,-4760.02 14241.38,-4760.02 14241.38,6719.88 -1558.53,6719.88 -1558.53,-4760.02 ; -1458.27,-4660.31 14141.12,-4660.31 14141.12,6620.18 -1458.27,6620.18 -1458.27,-4660.31
  lines w3.94: -1458.62,-4309.36 5231.38,-4309.36 ; -1458.27,-4130.12 411.38,-4130.12 ; -1458.27,-3950.12 5231.38,-3950.12 5231.38,-4660.31 ; 411.38,-4660.31 411.38,-3950.12 ; 411.38,-4190.12 5231.38,-4190.12 ; 411.38,-4070.12 5231.38,-4070.12 ; 1136.38,-4309.36 1136.38,-3950.12 ; 2726.38,-4309.36 2726.38,-3950.12 ; 3726.38,-4309.36 3726.38,-3950.12
  text "Designer:" at 5206.38,-4040.12 h100
  text "Sheet  1 of  1" at 1106.38,-4045.12 h100
  text ".Pcb_File_Name_No_Path" at 2501.38,-4045.12 h100
  text "File:" at 2701.38,-4045.12 h100
  text ".Version" at 3141.38,-4045.12 h100
  text "Revision:" at 3701.38,-4045.12 h100
  text ".Designer" at 4641.38,-4045.12 h100
  text "Code:" at 386.38,-4090.12 h100
  text ".Drawn_By" at 4641.38,-4160.12 h100
  text "Drawn By:" at 5206.38,-4160.12 h100
  text ".VariantName" at 2336.38,-4165.12 h100
  text "Variant:" at 2701.38,-4165.12 h100
  text "Date" at 3196.38,-4165.12 h100
  text "Modif. Date:" at 3701.38,-4165.12 h100
  text "ID:" at 381.38,-4270.12 h100
  text ".Approved_By" at 4641.38,-4280.12 h100
  text "Approved By:" at 5206.38,-4280.12 h100
  text "Size:  A3 H" at 1106.38,-4285.12 h100
  text "Signature:" at 2701.38,-4285.12 h100
  text ".Print_Date" at 3196.38,-4285.12 h100
  text "Print Date:" at 3701.38,-4285.12 h100
  text "Title:" at 5206.38,-4410.12 h100
  text "University of Hawaii at Manoa" at 378.03,-4422.52 h100
  text "High Energy Physics Group" at 378.03,-4520.95 h100
  text ".Printout_Name" at 4981.38,-4550.12 h160
  text "Instrumentation Development Laboratory" at 378.03,-4623.31 h100
FabNTop:
  text ".IDLnum" at 12596.73,-4090.31 h160
  text "ASSEMBLY" at 11576.77,-4166.61 h100
  text ".BoardName" at 12596.73,-4270.31 h160
FabNBot:
  text ".IDLnum" at 86.38,-4090.12 h160
  text "ASSEMBLY" at 1106.3,-4166.61 h100
  text ".BoardName" at 86.38,-4270.12 h160
PCBNTop:
  text ".IDLnum" at 12596.73,-4090.31 h160
  text "PCB" at 11576.77,-4166.61 h100
  text ".BoardName" at 12596.73,-4270.31 h160
PCBNBot:
  text ".IDLnum" at 86.62,-4089.84 h160
  text "PCB" at 1106.3,-4166.61 h100
  text ".BoardName" at 86.38,-4270.12 h160
Drill Drawing:
  drawing of 397 lines, arcs and shapes, not listed
  text "Notes:" at 8284.95,5012.51 h130
  text "1. Board shall be fabricated - performace class II as per IPC-6011 and IPC6012" at 8284.95,4887.51 h100
  text "2. Silkscreen printed on both sides" at 8284.95,4777.51 h100
  text "3. Material: high temperature FR4 class epoxy glass rated UL94V-0. UL symbol and rating shall be marked farside" at 8284.95,4652.51 h100
  text "35um copper for external layers and 18um for all internal layers" at 8384.96,4552.51 h100
  text "Must be RoHS compliant and survive a lead-free assembly max reflow of 260 deg C (5 passes)" at 8384.95,4452.51 h100
  text "Td rating: >340 deg C" at 8434.95,4327.51 h100
  text "Tg = 150 deg C (min)" at 8438.98,4217.24 h100
  text "4. Solder mask: SMOBC per IPC-SM-840C, class T must be Rohs compliant, 0.001\" max measured over bare copper plating," at 8284.95,3977.51 h100
  text "must clear all lands as indicated on gerber solder mask layers, color= GREEN" at 8384.95,3877.51 h100
  text "5. Finish: electro-less nickel immersion gold (ENIG), 0.05-0.125um Au over 3-6um Ni - over bare copper only" at 8284.73,3723.69 h100
  text "6. Solderability test: Category 2 of J-STD-003" at 8284.95,3577.51 h100
  text "7. Finished boards shall not have nicks, scratches, voids, exposed copper, poor plating or misdrilled holes" at 8284.95,3427.51 h100
  text "8. All holes sizes are after plating" at 8284.95,3277.51 h100
  text "9. PCB manufacturer may add copper thieving as needed to improve manufacturability," at 8234.95,3127.51 h100
  text "thieving to be 0.030\" round pads at 0.050\" spacing." at 8384.95,3027.51 h100
  text "Thieving will have a minimum of 0.100\" clearance from existing copper and should not be placed under surface mounted devices" at 8384.95,2927.51 h100
  text "10. PCB manufacturer may use tear drops to improve annular rings as long as DRC rules are followed" at 8239.95,2787.51 h100
  text "11. All via connections to power and ground planes are solid" at 8239.95,2647.51 h100
  text "12. All unconnected pads on inner signal layers are removed" at 8239.95,2507.51 h100
  text "13. All finished boards are to be 100% electrically tested" at 8239.96,2367.51 h100
  text "14. Unless otherwise indicated, all linear toleracnes shall be XX.X +/-0.2mm and XX.XX +/- 0.1mm" at 8239.95,2227.51 h100
  text "15. Gerber file GM1 shows board outline (milling line)" at 8239.94,2087.49 h100
  text "16. Table 1 shows Layer stack details" at 8239.93,1947.47 h100
  text "Table 1a: Layer Stack Details for IDL_16_016 (Imperial Units)" at 8228.35,782.21 h98.43
  text "Layer" at 8280.09,617.5 h60
  text "Name" at 8690,617.5 h60
  text "Material" at 9919.65,617.5 h60
  text "Thickness" at 10779.41,617.5 h60
  text "Constant" at 11429.25,617.5 h60
  text "Board Layer Stack" at 11999.11,617.5 h60
  text "1" at 8280.09,497.5 h60
  text "Top Overlay" at 8690,497.5 h60
  text "2" at 8280.09,377.5 h60
  text "Top Solder" at 8690,377.5 h60
  text "Solder Resist" at 9919.65,377.5 h60
  text "0.40mil" at 10779.41,377.5 h60
  text "3.5" at 11429.25,377.5 h60
  text "3" at 8280.09,257.5 h60
  text "Top Layer - SIG1" at 8690,257.5 h60
  text "Copper" at 9919.65,257.5 h60
  text "1.38mil" at 10779.41,257.5 h60
  text "4" at 8280.09,137.5 h60
  text "Dielectric 1" at 8690,137.5 h60
  text "FR-4" at 9919.65,137.5 h60
  text "8.00mil" at 10779.41,137.5 h60
  text "4.65" at 11429.25,137.5 h60
  text "5" at 8280.09,17.5 h60
  text "MID1_GND" at 8690,17.5 h60
  text "Copper" at 9919.65,17.5 h60
  text "0.71mil" at 10779.41,17.5 h60
  text "6" at 8280.09,-102.5 h60
  text "Dielectric 2" at 8690,-102.5 h60
  text "FR-4" at 9919.65,-102.5 h60
  text "40.00mil" at 10779.41,-102.5 h60
  text "4.65" at 11429.25,-102.5 h60
  text "7" at 8280.09,-222.5 h60
  text "MID2_PWR" at 8690,-222.5 h60
  text "Copper" at 9919.65,-222.5 h60
  text "0.71mil" at 10779.41,-222.5 h60
  text "8" at 8280.09,-342.5 h60
  text "Dielectric 4" at 8690,-342.5 h60
  text "FR-4" at 9919.65,-342.5 h60
  text "8.00mil" at 10779.41,-342.5 h60
  text "4.2" at 11429.25,-342.5 h60
  text "9" at 8280.09,-462.5 h60
  text "Bottom Layer - SIG2" at 8690,-462.5 h60
  text "Copper" at 9919.65,-462.5 h60
  text "1.38mil" at 10779.41,-462.5 h60
  text "10" at 8280.09,-582.5 h60
  text "Bottom Solder" at 8690,-582.5 h60
  text "Solder Resist" at 9919.65,-582.5 h60
  text "0.40mil" at 10779.41,-582.5 h60
  text "3.5" at 11429.25,-582.5 h60
  text "11" at 8280.09,-702.5 h60
  text "Bottom Overlay" at 8690,-702.5 h60
  text "Table 2: NC Drill Details for IDL_16_016" at 8228.35,-1658.74 h98.43
  text "Symbol" at 8317.5,-1800 h72
  text "Count" at 8823.38,-1800 h72
  text "Hole Size" at 9413.22,-1800 h72
  text "Plated" at 10562.88,-1800 h72
  text "Hole Type" at 11068.76,-1800 h72
  text "188" at 8823.38,-1950 h60
  text "12.00mil (0.305mm)" at 9413.22,-1950 h60
  text "PTH" at 10562.88,-1950 h60
  text "Round" at 11068.76,-1950 h60
  text "136" at 8823.38,-2100 h60
  text "15.75mil (0.400mm)" at 9413.22,-2100 h60
  text "PTH" at 10562.88,-2100 h60
  text "Round" at 11068.76,-2100 h60
  text "15" at 8823.38,-2250 h60
  text "33.07mil (0.840mm)" at 9413.22,-2250 h60
  text "PTH" at 10562.88,-2250 h60
  text "Round" at 11068.76,-2250 h60
  text "128" at 8823.38,-2400 h60
  text "39.37mil (1.000mm)" at 9413.22,-2400 h60
  text "PTH" at 10562.88,-2400 h60
  text "Round" at 11068.76,-2400 h60
  text "18" at 8823.38,-2550 h60
  text "40.00mil (1.016mm)" at 9413.22,-2550 h60
  text "PTH" at 10562.88,-2550 h60
  text "Round" at 11068.76,-2550 h60
  text "10" at 8823.38,-2700 h60
  text "45.00mil (1.143mm)" at 9413.22,-2700 h60
  text "PTH" at 10562.88,-2700 h60
  text "Round" at 11068.76,-2700 h60
  text "4" at 8823.38,-2850 h60
  text "66.93mil (1.700mm)" at 9413.22,-2850 h60
  text "NPTH" at 10562.88,-2850 h60
  text "Round" at 11068.76,-2850 h60
  text "4" at 8823.38,-3000 h60
  text "78.74mil (2.000mm)" at 9413.22,-3000 h60
  text "PTH" at 10562.88,-3000 h60
  text "Round" at 11068.76,-3000 h60
  text "2" at 8823.38,-3150 h60
  text "98.43mil (2.500mm)" at 9413.22,-3150 h60
  text "NPTH" at 10562.88,-3150 h60
  text "Round" at 11068.76,-3150 h60
  text "4" at 8823.38,-3300 h60
  text "137.80mil (3.500mm)" at 9413.22,-3300 h60
  text "NPTH" at 10562.88,-3300 h60
  text "Round" at 11068.76,-3300 h60
  text "2" at 8823.38,-3450 h60
  text "137.80mil (3.500mm)" at 9413.22,-3450 h60
  text "PTH" at 10562.88,-3450 h60
  text "Round" at 11068.76,-3450 h60
  text "5" at 8823.38,-3600 h60
  text "150.00mil (3.810mm)" at 9413.22,-3600 h60
  text "PTH" at 10562.88,-3600 h60
  text "Round" at 11068.76,-3600 h60
  text "516 Total" at 8823.38,-3750 h60

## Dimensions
4921.26,4921.26 to 4921.26,0 on Drill Drawing
0,4921.26 to 4921.26,4921.26 on Dimensions
4921.26,4921.26 to 4921.26,0 on Dimensions
0,4921.26 to 4921.26,4921.26 on Drill Drawing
